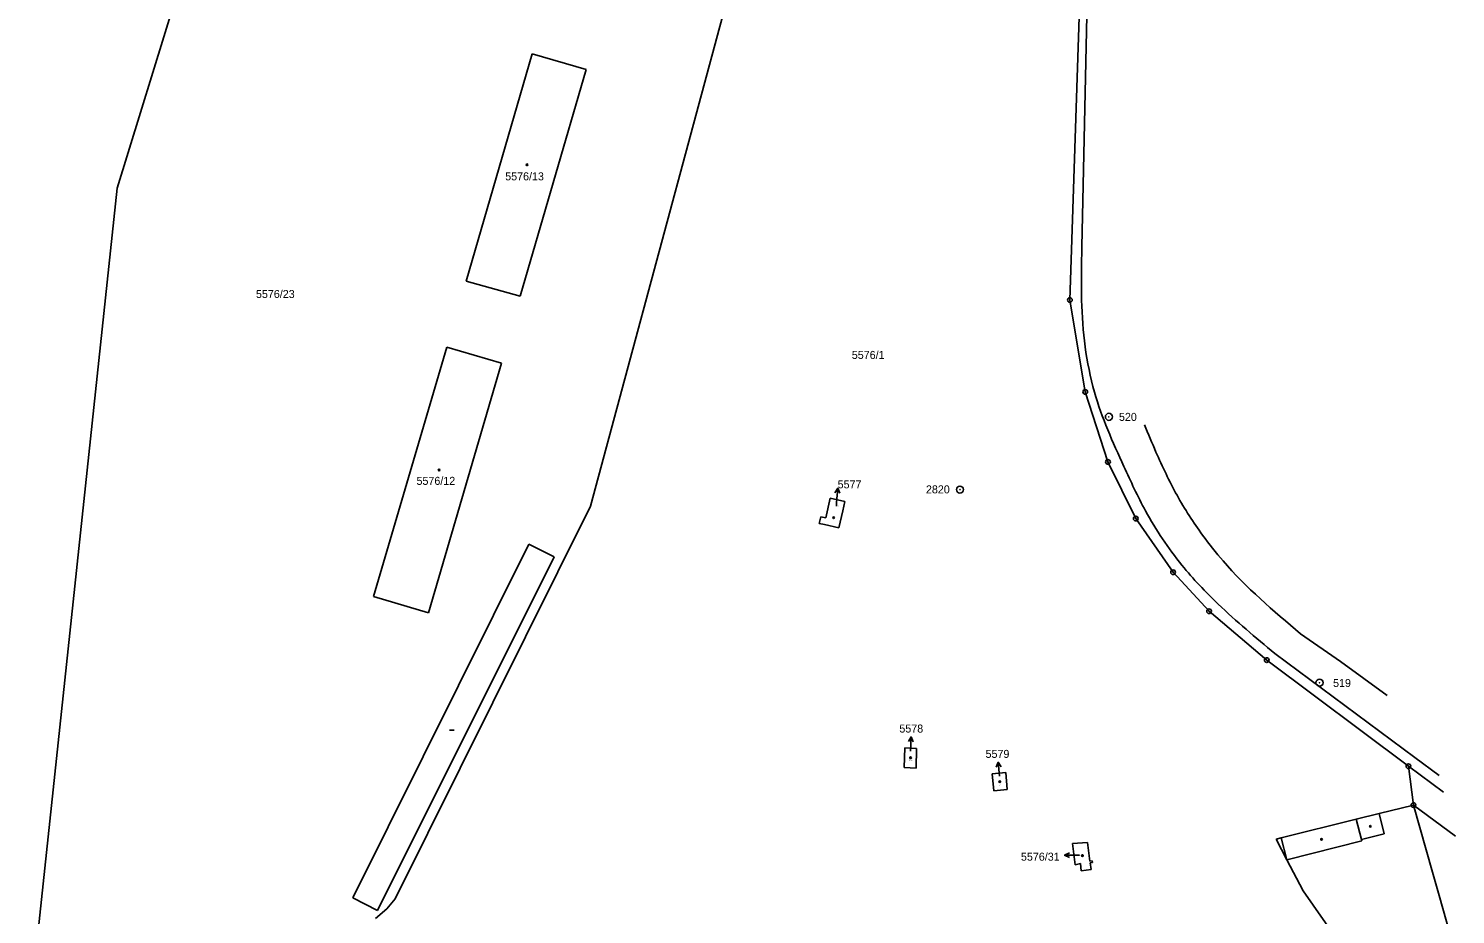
# Model space of a CAD drawing. Extents: x -825057 to -819383, y -1071633 to -1067888.
# Drawn here: x -820645.6 to -820342.6, y -1068368.2 to -1068180 of the extents above; entities that cross this region are included whole.
import ezdxf

# ---------------------------------------------------------------- set-up
doc = ezdxf.new("R2010")
doc.units = 0
for name, color, linetype in [('Vrstva 1', 7, 'Continuous'), ('Vrstva 16', 7, 'Continuous'), ('Vrstva 17', 7, 'Continuous'), ('Vrstva 18', 7, 'Continuous'), ('Vrstva 19', 7, 'Continuous'), ('Vrstva 24', 7, 'Continuous'), ('Vrstva 25', 7, 'Continuous'), ('Vrstva 4', 7, 'Continuous')]:
    doc.layers.add(name, color=color, linetype=linetype)

msp = doc.modelspace()

# ---------------------------------------------------------------- linework, layer by layer
at = {"layer": 'Vrstva 1'}
for p, q in [((-820585.41, -1068079.35), (-820626.81, -1068213.86)), ((-820526.3, -1068281.47), (-820479.5, -1068107.74)), ((-820421.73, -1068153.42), (-820424.47, -1068237.64)), ((-820538.64, -1068185.35), (-820552.69, -1068233.61)), ((-820527.19, -1068188.69), (-820538.64, -1068185.35)), ((-820541.22, -1068236.83), (-820527.19, -1068188.69)), ((-820626.81, -1068213.86), (-820645.63, -1068390.93)), ((-820552.69, -1068233.61), (-820541.22, -1068236.83)), ((-820424.47, -1068237.64), (-820421.2, -1068257.17)), ((-820556.79, -1068247.66), (-820572.36, -1068300.65)), ((-820545.15, -1068251.08), (-820556.79, -1068247.66)), ((-820560.68, -1068304.09), (-820545.15, -1068251.08)), ((-820421.2, -1068257.17), (-820416.37, -1068272.04)), ((-820416.37, -1068272.04), (-820410.47, -1068284.07)), ((-820476.3, -1068283.91), (-820475.39, -1068279.72)), ((-820475.39, -1068279.72), (-820472.24, -1068280.45)), ((-820567.75, -1068364.82), (-820526.3, -1068281.47)), ((-820472.71, -1068282.44), (-820473.55, -1068286.04)), ((-820472.24, -1068280.45), (-820472.71, -1068282.44)), ((-820477.69, -1068285.13), (-820477.36, -1068283.67)), ((-820476.58, -1068285.36), (-820477.69, -1068285.13)), ((-820477.36, -1068283.67), (-820476.3, -1068283.91)), ((-820473.55, -1068286.04), (-820476.58, -1068285.36)), ((-820410.47, -1068284.07), (-820402.54, -1068295.48)), ((-820402.54, -1068295.48), (-820394.9, -1068303.76)), ((-820572.36, -1068300.65), (-820560.68, -1068304.09)), ((-820394.9, -1068303.76), (-820382.65, -1068314.15)), ((-820382.65, -1068314.15), (-820352.57, -1068336.68)), ((-820459.51, -1068332.78), (-820459.65, -1068336.96)), ((-820459.51, -1068332.78), (-820457.01, -1068332.89)), ((-820457.01, -1068332.89), (-820457.08, -1068337.06)), ((-820457.08, -1068337.06), (-820459.65, -1068336.96)), ((-820352.57, -1068336.68), (-820351.5, -1068344.95)), ((-820352.57, -1068336.68), (-820345.1, -1068342.19)), ((-820440.94, -1068338.27), (-820438.08, -1068338.03)), ((-820440.63, -1068341.89), (-820440.94, -1068338.27)), ((-820438.08, -1068338.03), (-820437.78, -1068341.63)), ((-820437.78, -1068341.63), (-820440.63, -1068341.89)), ((-820358.79, -1068346.72), (-820363.64, -1068347.91)), ((-820351.5, -1068344.95), (-820358.79, -1068346.72)), ((-820351.5, -1068344.95), (-820347.46, -1068359.19)), ((-820351.5, -1068344.95), (-820342.57, -1068351.57)), ((-820363.64, -1068347.91), (-820379.56, -1068351.91)), ((-820420.73, -1068352.9), (-820423.94, -1068353.12)), ((-820423.94, -1068353.12), (-820423.32, -1068357.6)), ((-820420.19, -1068356.82), (-820420.73, -1068352.9)), ((-820379.56, -1068351.91), (-820380.67, -1068352.19)), ((-820380.67, -1068352.19), (-820378.39, -1068356.55)), ((-820423.32, -1068357.6), (-820422.23, -1068357.33)), ((-820422.23, -1068357.33), (-820422.1, -1068358.91)), ((-820422.1, -1068358.91), (-820419.92, -1068358.62)), ((-820419.74, -1068356.76), (-820420.19, -1068356.82)), ((-820420.14, -1068357.21), (-820419.69, -1068357.15)), ((-820419.92, -1068358.62), (-820420.14, -1068357.21)), ((-820419.69, -1068357.15), (-820419.74, -1068356.76)), ((-820378.39, -1068356.55), (-820374.95, -1068363.14)), ((-820347.46, -1068359.19), (-820346.05, -1068364.17)), ((-820569.56, -1068367), (-820567.75, -1068364.82)), ((-820374.95, -1068363.14), (-820368.03, -1068373.03)), ((-820346.05, -1068364.17), (-820343.7, -1068372.44)), ((-820571.92, -1068369.04), (-820569.56, -1068367))]:
    msp.add_line(p, q, dxfattribs=at)
at = {"layer": 'Vrstva 16'}
for p, q in [((-820474, -1068280.64), (-820473.78, -1068277.648)), ((-820474, -1068280.64), (-820473.78, -1068277.648)), ((-820474.06, -1068281.46), (-820474, -1068280.64)), ((-820474.06, -1068281.46), (-820474, -1068280.64)), ((-820458.33, -1068333.45), (-820458.197, -1068330.453)), ((-820458.33, -1068333.45), (-820458.197, -1068330.453)), ((-820439.42, -1068338.82), (-820439.672, -1068335.831)), ((-820439.42, -1068338.82), (-820439.672, -1068335.831)), ((-820422.57, -1068355.58), (-820425.57, -1068355.58)), ((-820422.57, -1068355.58), (-820425.57, -1068355.58)), ((-820422.44, -1068355.58), (-820422.57, -1068355.58)), ((-820422.44, -1068355.58), (-820422.57, -1068355.58))]:
    msp.add_line(p, q, dxfattribs=at)
for points in [[(-820474.352, -1068278.609), (-820473.78, -1068277.648), (-820473.355, -1068278.682)], [(-820474.352, -1068278.609), (-820473.78, -1068277.648), (-820473.355, -1068278.682)], [(-820458.741, -1068331.43), (-820458.197, -1068330.453), (-820457.742, -1068331.474)], [(-820458.741, -1068331.43), (-820458.197, -1068330.453), (-820457.742, -1068331.474)], [(-820440.086, -1068336.869), (-820439.672, -1068335.831), (-820439.09, -1068336.785)], [(-820440.086, -1068336.869), (-820439.672, -1068335.831), (-820439.09, -1068336.785)], [(-820424.57, -1068356.08), (-820425.57, -1068355.58), (-820424.57, -1068355.08)], [(-820424.57, -1068356.08), (-820425.57, -1068355.58), (-820424.57, -1068355.08)]]:
    msp.add_lwpolyline(points, dxfattribs=at)
at = {"layer": 'Vrstva 24'}
for centre, radius in [((-820424.47, -1068237.64), 0.5), ((-820424.47, -1068237.64), 0.5), ((-820424.47, -1068237.64), 0.0327), ((-820424.47, -1068237.64), 0.0327), ((-820421.2, -1068257.17), 0.5), ((-820421.2, -1068257.17), 0.5), ((-820421.2, -1068257.17), 0.0327), ((-820421.2, -1068257.17), 0.0327), ((-820416.18, -1068262.46), 0.75), ((-820416.18, -1068262.46), 0.75), ((-820416.18, -1068262.46), 0.0327), ((-820416.18, -1068262.46), 0.0327), ((-820416.37, -1068272.04), 0.5), ((-820416.37, -1068272.04), 0.5), ((-820416.37, -1068272.04), 0.0327), ((-820416.37, -1068272.04), 0.0327), ((-820447.81, -1068277.92), 0.75), ((-820447.81, -1068277.92), 0.75), ((-820447.81, -1068277.92), 0.0327), ((-820447.81, -1068277.92), 0.0327), ((-820410.47, -1068284.07), 0.5), ((-820410.47, -1068284.07), 0.5), ((-820410.47, -1068284.07), 0.0327), ((-820410.47, -1068284.07), 0.0327), ((-820402.54, -1068295.48), 0.5), ((-820402.54, -1068295.48), 0.5), ((-820402.54, -1068295.48), 0.0327), ((-820402.54, -1068295.48), 0.0327), ((-820394.9, -1068303.76), 0.5), ((-820394.9, -1068303.76), 0.5), ((-820394.9, -1068303.76), 0.0327), ((-820394.9, -1068303.76), 0.0327), ((-820382.65, -1068314.15), 0.5), ((-820382.65, -1068314.15), 0.5), ((-820382.65, -1068314.15), 0.0327), ((-820382.65, -1068314.15), 0.0327), ((-820371.44, -1068318.94), 0.75), ((-820371.44, -1068318.94), 0.75), ((-820371.44, -1068318.94), 0.0327), ((-820371.44, -1068318.94), 0.0327), ((-820352.57, -1068336.68), 0.5), ((-820352.57, -1068336.68), 0.5), ((-820352.57, -1068336.68), 0.0327), ((-820352.57, -1068336.68), 0.0327), ((-820351.5, -1068344.95), 0.5), ((-820351.5, -1068344.95), 0.5), ((-820351.5, -1068344.95), 0.0327), ((-820351.5, -1068344.95), 0.0327)]:
    msp.add_circle(centre, radius, dxfattribs=at)
at = {"layer": 'Vrstva 25'}
msp.add_line((-820556.21, -1068329.03), (-820555.21, -1068329.03), dxfattribs=at)
msp.add_line((-820556.21, -1068329.03), (-820555.21, -1068329.03), dxfattribs=at)
for centre in [(-820539.77, -1068208.92), (-820539.77, -1068208.92), (-820558.43, -1068273.77), (-820558.43, -1068273.77), (-820474.64, -1068283.89), (-820474.64, -1068283.89), (-820458.31, -1068334.89), (-820458.31, -1068334.89), (-820439.35, -1068339.96), (-820439.35, -1068339.96), (-820360.64, -1068349.44), (-820360.64, -1068349.44), (-820371.01, -1068352.23), (-820371.01, -1068352.23), (-820421.79, -1068355.68), (-820421.79, -1068355.68)]:
    msp.add_circle(centre, 0.175, dxfattribs=at)
at = {"layer": 'Vrstva 4'}
for p, q in [((-820420.81, -1068173.9), (-820421.91, -1068226.33)), ((-820539.38, -1068289.51), (-820576.72, -1068364.67)), ((-820533.99, -1068292.2), (-820539.38, -1068289.51)), ((-820571.52, -1068367.31), (-820533.99, -1068292.2)), ((-820366.96, -1068314.45), (-820375.45, -1068308.56)), ((-820380.92, -1068312.77), (-820351.19, -1068334.84)), ((-820357.11, -1068321.63), (-820366.96, -1068314.45)), ((-820351.19, -1068334.84), (-820346.05, -1068338.67)), ((-820358.79, -1068346.72), (-820357.71, -1068351.02)), ((-820363.64, -1068347.91), (-820362.55, -1068352.24)), ((-820378.39, -1068356.55), (-820379.56, -1068351.91)), ((-820362.47, -1068352.55), (-820378.39, -1068356.55)), ((-820357.71, -1068351.02), (-820362.55, -1068352.24)), ((-820362.55, -1068352.24), (-820362.47, -1068352.55)), ((-820576.72, -1068364.67), (-820571.52, -1068367.31))]:
    msp.add_line(p, q, dxfattribs=at)
for points in [[(-820421.91, -1068226.33), (-820421.97, -1068237.7), (-820419.24, -1068257.22), (-820412.99, -1068273.01), (-820408.4, -1068282.43), (-820400.65, -1068293.99), (-820392.97, -1068302.23), (-820380.92, -1068312.77)], [(-820375.45, -1068308.56), (-820391.93, -1068293.08), (-820396.27, -1068287.59), (-820401.7, -1068279.13), (-820406.18, -1068269.93), (-820408.64, -1068264.16)]]:
    msp.add_spline(points, degree=3, dxfattribs=at)

# ---------------------------------------------------------------- texts
at = {"layer": 'Vrstva 16'}
for s, p in [('5577', (-820473.78, -1068277.65)), ('5577', (-820473.78, -1068277.65)), ('5578', (-820460.677, -1068329.53)), ('5578', (-820460.677, -1068329.53)), ('5579', (-820442.37, -1068334.91)), ('5579', (-820442.37, -1068334.91)), ('5576/31', (-820434.855, -1068356.75)), ('5576/31', (-820434.855, -1068356.75))]:
    msp.add_text(s, height=1.7, dxfattribs=at).set_placement(p)
at = {"layer": 'Vrstva 17'}
for s, p in [('520', (-820414.036, -1068263.32)), ('520', (-820414.036, -1068263.32)), ('2820', (-820455.03, -1068278.72)), ('2820', (-820455.03, -1068278.72)), ('519', (-820368.562, -1068319.85)), ('519', (-820368.562, -1068319.85))]:
    msp.add_text(s, height=1.7, dxfattribs=at).set_placement(p)
at = {"layer": 'Vrstva 18'}
for s, p in [('5576/23', (-820597.324, -1068237.21)), ('5576/23', (-820597.324, -1068237.21)), ('5576/1', (-820470.778, -1068250.16)), ('5576/1', (-820470.778, -1068250.16))]:
    msp.add_text(s, height=1.7, dxfattribs=at).set_placement(p)
at = {"layer": 'Vrstva 19'}
for s, height, p in [('5576/13', 1.7, (-820544.392, -1068212.22)), ('5576/13', 1.7, (-820544.392, -1068212.22)), ('5576/12', 1.7, (-820563.23, -1068276.91)), ('5576/12', 1.7, (-820563.23, -1068276.91)), ('5577', 0.2, (-820474.06, -1068281.46)), ('5577', 0.2, (-820474.06, -1068281.46)), ('5578', 0.2, (-820458.554, -1068335.5)), ('5578', 0.2, (-820458.554, -1068335.5)), ('5579', 0.2, (-820439.622, -1068340.77)), ('5579', 0.2, (-820439.622, -1068340.77)), ('5576/31', 0.2, (-820422.44, -1068355.58)), ('5576/31', 0.2, (-820422.44, -1068355.58))]:
    msp.add_text(s, height=height, dxfattribs=at).set_placement(p)

doc.saveas('drawing.dxf')
